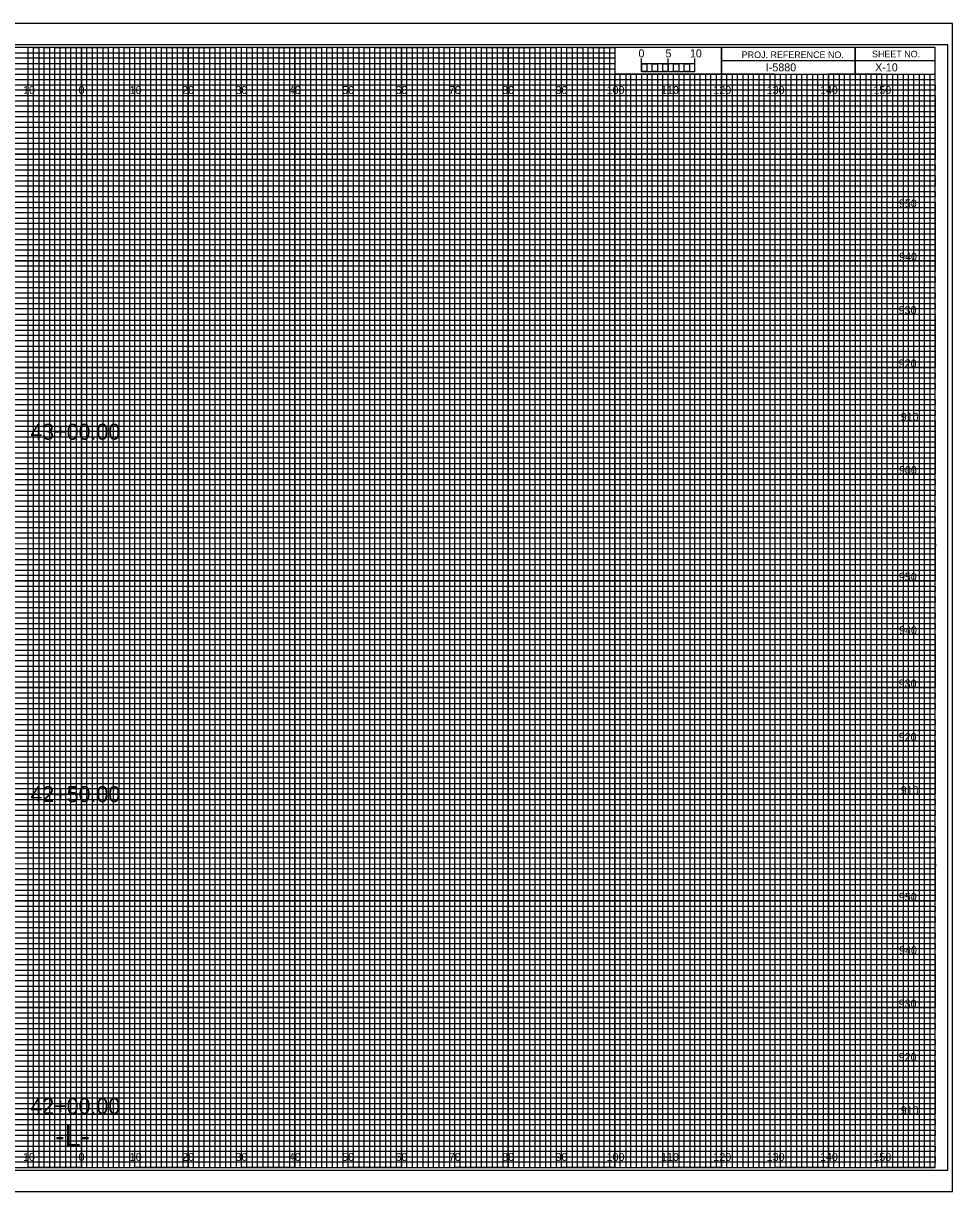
# Model space of a CAD drawing. Extents: x -13 to 323, y -4 to 3074.
# Drawn here: x 149.1 to 323.3, y 1755.5 to 1974.5 of the extents above; entities that cross this region are included whole.
import ezdxf

# ---------------------------------------------------------------- set-up
doc = ezdxf.new("R2010")
doc.units = 0
for name, color, linetype in [('Prop XS Alignment Label', 7, 'Continuous'), ('Prop XS Bar Scale Labels', 7, 'Continuous'), ('Prop XS Elevation Labels', 7, 'Continuous'), ('Prop XS Offset Labels', 7, 'Continuous'), ('Prop XS Project Number', 7, 'Continuous'), ('Prop XS Sheet Number', 7, 'Continuous'), ('Prop XS Station Labels', 7, 'Continuous'), ('Sheet Cross Section CELL', 7, 'Continuous'), ('Sheet Cross Section Grid Major CELL', 7, 'Continuous'), ('Sheet Cross Section Grid Middle CELL', 7, 'Continuous'), ('Sheet Cross Section Grid Minor 1 CELL', 7, 'Continuous'), ('Sheet Cross Section Grid Minor 2 CELL', 7, 'Continuous'), ('Sheet Cross Section Scale CELL', 7, 'Continuous'), ('Sheet Cutting Line CELL', 7, 'Continuous'), ('Sheet DOT Grid CELL', 7, 'Continuous'), ('Sheet Plot Border Inside CELL', 7, 'Continuous'), ('Sheet Plot Border Outside CELL', 7, 'Continuous')]:
    doc.layers.add(name, color=color, linetype=linetype)

msp = doc.modelspace()

# ---------------------------------------------------------------- linework, layer by layer
at = {"layer": 'Sheet Cross Section CELL'}
for p, q in [((305, 1970), (305, 1965)), ((305, 1965), (305, 1970)), ((280, 1967.5), (280, 1965)), ((320, 1967.49), (280, 1967.49)), ((280, 1965), (320, 1965))]:
    msp.add_line(p, q, dxfattribs=at)
for points in [[(320, 1970), (0, 1970), (0, 1760), (320, 1760)], [(280, 1970), (260, 1970), (260, 1965.03), (280, 1965.03)], [(320, 1970), (280, 1970), (280, 1965), (320, 1965)]]:
    msp.add_lwpolyline(points, close=True, dxfattribs=at)
at = {"layer": 'Sheet Cross Section Grid Major CELL'}
for p, q in [((150, 1970), (140, 1970)), ((150, 1760), (150, 1970)), ((170, 1970), (160, 1970)), ((160, 1970), (160, 1760)), ((170, 1760), (170, 1970)), ((190, 1970), (180, 1970)), ((180, 1970), (180, 1760)), ((190, 1760), (190, 1970)), ((210, 1970), (200, 1970)), ((200, 1970), (200, 1760)), ((210, 1760), (210, 1970)), ((230, 1970), (220, 1970)), ((220, 1970), (220, 1760)), ((230, 1760), (230, 1970)), ((250, 1970), (240, 1970)), ((240, 1970), (240, 1760)), ((250, 1760), (250, 1970)), ((260, 1970), (260, 1760)), ((270, 1760), (270, 1965)), ((290, 1965), (280, 1965)), ((280, 1965), (280, 1760)), ((290, 1760), (290, 1965)), ((310, 1965), (300, 1965)), ((300, 1965), (300, 1760)), ((310, 1760), (310, 1965)), ((160, 1760), (150, 1760)), ((180, 1760), (170, 1760)), ((200, 1760), (190, 1760)), ((220, 1760), (210, 1760)), ((240, 1760), (230, 1760)), ((260, 1760), (250, 1760)), ((280, 1760), (270, 1760)), ((300, 1760), (290, 1760)), ((320, 1760), (310, 1760)), ((320, 1760), (320, 1760))]:
    msp.add_line(p, q, dxfattribs=at)
for points in [[(0, 1960), (320, 1960), (320, 1950), (0, 1950)], [(0, 1940), (320, 1940), (320, 1930), (0, 1930)], [(0, 1920), (320, 1920), (320, 1910), (0, 1910)], [(0, 1900), (320, 1900), (320, 1890), (0, 1890)], [(0, 1880), (320, 1880), (320, 1870), (0, 1870)], [(0, 1860), (320, 1860), (320, 1850), (0, 1850)], [(0, 1840), (320, 1840), (320, 1830), (0, 1830)], [(0, 1820), (320, 1820), (320, 1810), (0, 1810)], [(0, 1800), (320, 1800), (320, 1790), (0, 1790)], [(0, 1780), (320, 1780), (320, 1770), (0, 1770)]]:
    msp.add_lwpolyline(points, dxfattribs=at)
at = {"layer": 'Sheet Cross Section Grid Middle CELL'}
for points in [[(145, 1760), (155, 1760), (155, 1970), (165, 1970), (165, 1760), (175, 1760), (175, 1970), (185, 1970), (185, 1760), (195, 1760), (195, 1970), (205, 1970), (205, 1760), (215, 1760), (215, 1970), (225, 1970), (225, 1760), (235, 1760), (235, 1970), (245, 1970), (245, 1760), (255, 1760), (255, 1970), (259.93, 1970), (260, 1970), (260, 1965), (264.99, 1965), (264.99, 1760), (275, 1760), (275, 1965), (285, 1965), (285, 1760), (295, 1760), (295, 1965), (305, 1965), (305, 1760), (315, 1760), (315, 1965)], [(0, 1965), (275, 1965)], [(0, 1945), (320, 1945), (320, 1955), (0, 1955)], [(0, 1925), (320, 1925), (320, 1935), (0, 1935)], [(0, 1905), (320, 1905), (320, 1915), (0, 1915)], [(0, 1885), (320, 1885), (320, 1895), (0, 1895)], [(0, 1865), (320, 1865), (320, 1875), (0, 1875)], [(0, 1845), (320, 1845), (320, 1855), (0, 1855)], [(0, 1825), (320, 1825), (320, 1835), (0, 1835)], [(0, 1805), (320, 1805), (320, 1815), (0, 1815)], [(0, 1785), (320, 1785), (320, 1795), (0, 1795)], [(0, 1765), (320, 1765), (320, 1775), (0, 1775)]]:
    msp.add_lwpolyline(points, dxfattribs=at)
at = {"layer": 'Sheet Cross Section Grid Minor 1 CELL'}
for p, q in [((0, 1969), (260, 1969)), ((260, 1969), (260, 1967.98)), ((260, 1967.98), (0, 1967.98)), ((0, 1967), (260, 1967)), ((260, 1967), (260, 1965.89)), ((260, 1965.89), (0, 1965.89)), ((0, 1964), (320, 1964))]:
    msp.add_line(p, q, dxfattribs=at)
for points in [[(0, 1963), (270, 1963), (320, 1963), (320, 1962), (0, 1962)], [(0, 1961), (320, 1961), (320, 1959), (0, 1959)], [(0, 1958), (320, 1958), (320, 1957), (0, 1956.98)], [(0, 1956), (320, 1956), (320, 1954), (0, 1954)], [(0, 1953), (320, 1953), (320, 1952), (0, 1952)], [(0, 1951), (320, 1951), (320, 1949), (0, 1949)], [(0, 1948), (320, 1948), (320, 1947), (0, 1947)], [(0, 1946), (320, 1946), (320, 1944), (0, 1944)], [(0, 1943), (320, 1943), (320, 1942), (0, 1942)], [(0, 1941), (320, 1941), (320, 1939), (0, 1939)], [(0, 1938), (320, 1938), (320, 1937), (0, 1937)], [(0, 1936), (320, 1936), (320, 1933.95), (320, 1933), (320, 1932), (0, 1932)], [(0, 1934), (320, 1934), (320, 1933), (0, 1933)], [(0, 1931), (320, 1931), (320, 1929), (0, 1929.03)], [(0, 1929.03), (320, 1929), (320, 1928), (0, 1928)], [(0, 1927), (320, 1927), (320, 1926), (0, 1926)], [(0, 1924), (320, 1924), (320, 1923), (0, 1923)], [(0, 1922), (320, 1922), (320, 1921), (0, 1921)], [(-0.07, 1918.89), (320, 1918.89), (320, 1917.88), (-0.07, 1917.88)], [(0, 1917), (320, 1917), (320, 1916), (0, 1916)], [(0, 1914), (320, 1914), (320, 1913), (0, 1913)], [(0, 1912), (320, 1912), (320, 1911), (0, 1911)], [(0, 1909), (320, 1909), (320, 1908), (0, 1908)], [(0, 1907), (320, 1907), (320, 1906), (0, 1906)], [(0, 1904), (320, 1904), (320, 1903), (0, 1903)], [(0, 1902), (320, 1902), (320, 1901), (0, 1901)], [(0, 1899), (320, 1899), (319.99, 1897.98), (0, 1898)], [(0, 1897), (320, 1897), (320, 1896), (0, 1896)], [(0, 1894), (320, 1894), (320, 1893), (0, 1893)], [(0, 1892), (320, 1892), (320, 1891), (0, 1891)], [(0, 1889), (320, 1889), (320, 1888), (0, 1888)], [(0, 1887), (320, 1887), (320, 1886), (0, 1886)], [(0, 1884), (320, 1884), (320, 1883), (0, 1883)], [(0, 1882), (320, 1882), (320, 1881), (0, 1881)], [(0, 1879), (320, 1879), (320, 1878), (0, 1878)], [(0, 1876.99), (320.07, 1876.91), (320, 1876), (0, 1876)], [(0, 1874), (320, 1874), (320, 1873), (0, 1873)], [(0, 1872), (320, 1872), (320, 1871), (0, 1871)], [(0, 1869), (320, 1869), (320, 1868), (0, 1868)], [(0, 1867), (320, 1867), (320, 1866), (0, 1866)], [(0, 1864), (320, 1864), (320, 1863), (0, 1863)], [(0, 1862), (320, 1862), (320, 1861), (0, 1861)], [(0, 1859), (320, 1859), (320, 1858), (0, 1858)], [(0, 1857), (320, 1857), (320, 1856), (0, 1856)], [(0, 1854), (320, 1854), (320, 1853), (0, 1853)], [(0, 1852), (320, 1852), (320, 1851), (0, 1851)], [(0, 1849), (320, 1849), (320, 1848), (0, 1848)], [(0, 1847), (320, 1847), (320, 1846), (0, 1846)], [(0, 1844), (320, 1844), (320, 1843), (0, 1843)], [(0, 1842), (320, 1842), (320, 1841), (0, 1841)], [(0, 1839), (320, 1839), (319.99, 1837.98), (0, 1838)], [(0, 1837), (320, 1837), (320, 1836), (0, 1836)], [(0, 1834), (320, 1834), (320, 1833), (0, 1833)], [(0, 1832), (320, 1832), (320, 1831), (0, 1831)], [(0, 1829), (320, 1829), (320, 1828), (0, 1828)], [(0, 1827), (320, 1827), (320, 1826), (0, 1826)], [(0, 1824), (320, 1824), (320, 1823), (0, 1823)], [(0, 1822), (320, 1822), (320, 1821), (0, 1821)], [(0, 1819), (320, 1819), (320, 1818), (0, 1818)], [(0, 1816.99), (320.07, 1816.91), (320, 1816), (0, 1816)], [(0, 1814), (320, 1814), (320, 1813), (0, 1813)], [(0, 1812), (320, 1812), (320, 1811), (0, 1811)], [(0, 1809), (320, 1809), (320, 1808), (0, 1808)], [(0, 1807), (320, 1807), (320, 1806), (0, 1806)], [(0, 1804), (320, 1804), (320, 1803), (0, 1803)], [(0, 1802), (320, 1802), (320, 1801), (0, 1801)], [(0, 1799), (320, 1799), (320, 1798), (0, 1798)], [(0, 1797), (320, 1797), (320, 1796), (0, 1796)], [(0, 1794), (320, 1794), (320, 1793), (0, 1793)], [(0, 1792), (320, 1792), (320, 1791), (0, 1791)], [(0, 1789), (320, 1789), (320, 1788), (0, 1788)], [(0, 1787), (320, 1787), (320, 1786), (0, 1786)], [(0, 1784), (320, 1784), (320, 1783), (0, 1783)], [(0, 1782), (320, 1782), (320, 1781), (0, 1781)], [(0, 1779), (320, 1779), (320, 1778), (0, 1778)], [(0, 1777), (320, 1777), (320, 1776), (0, 1776)], [(0, 1774), (320, 1774), (320, 1773), (0, 1773)], [(0, 1772), (320, 1772), (320, 1771), (0, 1771)], [(0, 1769), (320, 1769), (320, 1768), (0, 1768)], [(0, 1767), (320, 1767), (320, 1766), (0, 1766)], [(0, 1764), (320, 1764), (320, 1763), (0, 1763)], [(0, 1762), (320, 1762), (320, 1761), (0, 1761)]]:
    msp.add_lwpolyline(points, dxfattribs=at)
at = {"layer": 'Sheet Cross Section Grid Minor 2 CELL'}
for p, q in [((267, 1965), (266.01, 1965)), ((266.01, 1965), (266.01, 1760)), ((267, 1760), (267, 1965)), ((269, 1965), (268, 1965)), ((268, 1965), (268, 1760)), ((269, 1760), (269, 1965)), ((266.01, 1760), (265, 1760)), ((268, 1760), (267, 1760))]:
    msp.add_line(p, q, dxfattribs=at)
for points in [[(150, 1760), (151, 1760), (151, 1970), (152, 1970), (152, 1760)], [(152, 1760), (153, 1760), (153, 1970), (154, 1970), (154, 1760)], [(155, 1760), (156, 1760), (156, 1970), (157, 1970), (157, 1760)], [(157, 1760), (158, 1760), (158, 1970), (159, 1970), (159, 1760)], [(160, 1760), (161, 1760), (161, 1970), (162, 1970), (162, 1760)], [(162, 1760), (163, 1760), (163, 1970), (164, 1970), (164, 1760)], [(165, 1760), (166, 1760), (166, 1970), (167, 1970), (167, 1760)], [(167, 1760), (168, 1760), (168, 1970), (169, 1970), (169, 1760)], [(170, 1760), (171, 1760), (171, 1970), (172, 1970), (172, 1760)], [(172, 1760), (173, 1760), (173, 1970), (174, 1970), (174, 1760)], [(175, 1760), (176, 1760), (176, 1970), (177, 1970), (177, 1760)], [(177, 1760), (178, 1760), (178, 1970), (179, 1970), (179, 1760)], [(180, 1760), (181, 1760), (181, 1970), (182, 1970), (182, 1760)], [(182, 1760), (183, 1760), (183, 1970), (184, 1970), (184, 1760)], [(185, 1760), (186, 1760), (186, 1970), (187, 1970), (187, 1760)], [(187, 1760), (188, 1760), (188, 1970), (189, 1970), (189, 1760)], [(190, 1760), (191, 1760), (191, 1970), (192, 1970), (192, 1760)], [(192, 1760), (193, 1760), (193, 1970), (194, 1970), (194, 1760)], [(195, 1760), (196, 1760), (196, 1970), (197, 1970), (197, 1760)], [(197, 1760), (198, 1760), (198, 1970), (199, 1970), (199, 1760)], [(200, 1760), (201, 1760), (201, 1970), (202, 1970), (202, 1760)], [(202, 1760), (203, 1760), (203, 1970), (204, 1970), (204, 1760)], [(205, 1760), (206, 1760), (206, 1970), (207, 1970), (207, 1760)], [(207, 1760), (208, 1760), (208, 1970), (209, 1970), (209, 1760)], [(210, 1760), (211, 1760), (211, 1970), (212, 1970), (212, 1760)], [(212, 1760), (213, 1760), (213, 1970), (214, 1970), (214, 1760)], [(215, 1760), (216, 1760), (216, 1970), (217, 1970), (217, 1760)], [(217, 1760), (218, 1760), (218, 1970), (219, 1970), (219, 1760)], [(220, 1760), (221, 1760), (221, 1970), (222, 1970), (222, 1760)], [(222, 1760), (223, 1760), (223, 1970), (224, 1970), (224, 1760)], [(225, 1760), (226, 1760), (226, 1970), (227, 1970), (227, 1760)], [(227, 1760), (228, 1760), (228, 1970), (229, 1970), (229, 1760)], [(230, 1760), (231, 1760), (231, 1970), (232, 1970), (232, 1760)], [(232, 1760), (233, 1760), (233, 1970), (234, 1970), (234, 1760)], [(235, 1760), (236, 1760), (236, 1970), (237, 1970), (237, 1760)], [(237, 1760), (238, 1760), (238, 1970), (239, 1970), (239, 1760)], [(240, 1760), (241, 1760), (241, 1970), (242, 1970), (242, 1760)], [(242, 1760), (243, 1760), (243, 1970), (244, 1970), (244, 1760)], [(245, 1760), (246, 1760), (246, 1970), (247, 1970), (247, 1760)], [(247, 1760), (248, 1760), (248, 1970), (249, 1970), (249, 1760)], [(250, 1760), (251, 1760), (251, 1970), (252, 1970), (252, 1760)], [(252, 1760), (253, 1760), (253, 1970), (254, 1970), (254, 1760)], [(255, 1760), (256, 1760), (256, 1970), (257, 1970), (257, 1760)], [(257, 1760), (258, 1760), (258, 1970), (259, 1970), (259, 1760)], [(260, 1760), (261, 1760), (261, 1965), (262.02, 1965), (262.02, 1760)], [(262, 1760), (263, 1760), (263, 1965), (263.99, 1965), (263.99, 1760)], [(270, 1760), (270.98, 1760), (270.98, 1965), (272, 1965), (272, 1760)], [(272, 1760), (273, 1760), (273, 1965), (274.05, 1965), (274.05, 1760)], [(275, 1760), (276, 1760), (276, 1965), (277, 1965), (277, 1760)], [(277, 1760), (278, 1760), (278, 1965), (279, 1965), (279, 1760)], [(280, 1760), (281, 1760), (281, 1965), (282, 1965), (282, 1760)], [(282, 1760), (283, 1760), (283, 1965), (284, 1965), (284, 1760)], [(285, 1760), (286, 1760), (286, 1965), (287, 1965), (287, 1760)], [(287, 1760), (288, 1760), (288, 1965), (289, 1965), (289, 1760)], [(290, 1760), (291, 1760), (291, 1965), (292, 1965), (292, 1760)], [(292, 1760), (293, 1760), (293, 1965), (294, 1965), (294, 1760)], [(295, 1760), (296, 1760), (296, 1965), (297, 1965), (297, 1760)], [(297, 1760), (298, 1760), (298, 1965), (299, 1965), (299, 1760)], [(300, 1760), (301, 1760), (301, 1965), (302, 1965), (302, 1760)], [(302, 1760), (303, 1760), (303, 1965), (304, 1965), (304, 1760)], [(305, 1760), (306, 1760), (306, 1965), (307, 1965), (307, 1760)], [(307, 1760), (308, 1760), (308, 1965), (309, 1965), (309, 1760)], [(310, 1760), (311, 1760), (311, 1965), (312, 1965), (312, 1760)], [(312, 1760), (313, 1760), (313, 1965), (314, 1965), (314, 1760)], [(315, 1760), (316, 1760), (316, 1965), (317, 1965), (317, 1760)], [(317, 1760), (318, 1760), (318, 1965), (319, 1965), (319, 1760)]]:
    msp.add_lwpolyline(points, dxfattribs=at)
at = {"layer": 'Sheet Cross Section Scale CELL'}
for p, q in [((265, 1965.49), (265, 1967.9)), ((265, 1966.9), (265, 1967.9)), ((270, 1965.49), (270, 1967.9)), ((275, 1965.49), (275, 1967.9)), ((275, 1966.9), (275, 1967.9))]:
    msp.add_line(p, q, dxfattribs=at)
for points in [[(275, 1966.9), (265, 1966.9), (265, 1965.49), (275, 1965.49)], [(265, 1966.9), (266, 1966.9), (266, 1965.49), (265, 1965.49)], [(267, 1966.9), (268, 1966.9), (268, 1965.49), (267, 1965.49)], [(269, 1966.9), (270, 1966.9), (270, 1965.49), (269, 1965.49)], [(271, 1966.9), (272, 1966.9), (272, 1965.49), (271, 1965.49)], [(273, 1966.9), (274, 1966.9), (274, 1965.49), (273, 1965.49)]]:
    msp.add_lwpolyline(points, close=True, dxfattribs=at)
at = {"layer": 'Sheet Cutting Line CELL'}
for p, q in [((323.3, 1974.5), (-13.4, 1974.5)), ((-13.4, 1755.5), (323.3, 1755.5))]:
    msp.add_line(p, q, dxfattribs=at)
at = {"layer": 'Sheet DOT Grid CELL'}
for p, q in [((150, 1760), (150, 1970)), ((160, 1760), (160, 1970)), ((170, 1760), (170, 1970)), ((180, 1760), (180, 1970)), ((190, 1760), (190, 1970)), ((200, 1760), (200, 1970)), ((210, 1760), (210, 1970)), ((220, 1760), (220, 1970)), ((230, 1760), (230, 1970)), ((240, 1760), (240, 1970)), ((250, 1760), (250, 1970)), ((260, 1760), (260, 1964.69)), ((270, 1760), (270, 1964.69)), ((280, 1760), (280, 1964.69)), ((290, 1760), (290, 1964.69)), ((300, 1760), (300, 1964.69)), ((310, 1760), (310, 1964.69)), ((0, 1960), (320, 1960)), ((0, 1950), (320, 1950)), ((0, 1940), (320, 1940)), ((0, 1930), (320, 1930)), ((0, 1920), (320, 1920)), ((0, 1910), (320, 1910)), ((0, 1900), (320, 1900)), ((0, 1890), (320, 1890)), ((0, 1880), (320, 1880)), ((0, 1870), (320, 1870)), ((0, 1860), (320, 1860)), ((0, 1850), (320, 1850)), ((0, 1840), (320, 1840)), ((0, 1830), (320, 1830)), ((0, 1820), (320, 1820)), ((0, 1810), (320, 1810)), ((0, 1800), (320, 1800)), ((0, 1790), (320, 1790)), ((0, 1780), (320, 1780)), ((0, 1770), (320, 1770))]:
    msp.add_line(p, q, dxfattribs=at)
at = {"layer": 'Sheet Plot Border Inside CELL'}
msp.add_lwpolyline([(-10.8, 1759.5), (322.4, 1759.5), (322.4, 1970.5), (-10.8, 1970.5)], close=True, dxfattribs=at)
at = {"layer": 'Sheet Plot Border Outside CELL'}
msp.add_lwpolyline([(-13.4, 1755.5), (323.3, 1755.5), (323.3, 1974.5), (-13.4, 1974.5)], close=True, dxfattribs=at)

# ---------------------------------------------------------------- texts
at = {"layer": 'Prop XS Alignment Label'}
msp.add_text('-L-', height=4, dxfattribs=at).set_placement((155.06, 1764))
at = {"layer": 'Prop XS Bar Scale Labels'}
for s, p in [('5', (269.47, 1968.12)), ('10', (274.04, 1968.12))]:
    msp.add_text(s, height=1.5, dxfattribs=at).set_placement(p)
at = {"layer": 'Prop XS Elevation Labels'}
for s, p in [('950', (313.22, 1940)), ('940', (313.26, 1930)), ('930', (313.18, 1920)), ('920', (313.19, 1910)), ('910', (313.57, 1900)), ('900', (313.24, 1890)), ('950', (313.22, 1870)), ('940', (313.26, 1860)), ('930', (313.18, 1850)), ('920', (313.19, 1840)), ('910', (313.57, 1830)), ('950', (313.22, 1810)), ('940', (313.26, 1800)), ('930', (313.18, 1790)), ('920', (313.19, 1780)), ('910', (313.57, 1770))]:
    msp.add_text(s, height=1.5, dxfattribs=at).set_placement(p)
at = {"layer": 'Prop XS Offset Labels'}
for s, p in [('10', (149.04, 1961.25)), ('0', (159.45, 1961.25)), ('0', (159.45, 1961.25)), ('10', (169.04, 1961.25)), ('20', (178.86, 1961.25)), ('30', (188.86, 1961.25)), ('40', (198.86, 1961.25)), ('50', (208.86, 1961.25)), ('60', (218.86, 1961.25)), ('70', (228.86, 1961.25)), ('80', (238.86, 1961.25)), ('90', (248.86, 1961.25)), ('100', (258.44, 1961.25)), ('110', (268.62, 1961.25)), ('120', (278.44, 1961.25)), ('130', (288.44, 1961.25)), ('140', (298.44, 1961.25)), ('150', (308.44, 1961.25)), ('10', (149.04, 1761.25)), ('0', (159.45, 1761.25)), ('0', (159.45, 1761.25)), ('10', (169.04, 1761.25)), ('20', (178.86, 1761.25)), ('30', (188.86, 1761.25)), ('40', (198.86, 1761.25)), ('50', (208.86, 1761.25)), ('60', (218.86, 1761.25)), ('70', (228.86, 1761.25)), ('80', (238.86, 1761.25)), ('90', (248.86, 1761.25)), ('100', (258.44, 1761.25)), ('110', (268.62, 1761.25)), ('120', (278.44, 1761.25)), ('130', (288.44, 1761.25)), ('140', (298.44, 1761.25)), ('150', (308.44, 1761.25))]:
    msp.add_text(s, height=1.5, dxfattribs=at).set_placement(p)
at = {"layer": 'Prop XS Project Number'}
msp.add_text('I-5880', height=1.5, dxfattribs=at).set_placement((288.28, 1965.5))
at = {"layer": 'Prop XS Sheet Number'}
msp.add_text('X-10', height=1.5, dxfattribs=at).set_placement((308.77, 1965.5))
at = {"layer": 'Prop XS Station Labels'}
for s, p in [('43+00.00', (150.41, 1896.45)), ('42+50.00', (150.41, 1828.52)), ('42+00.00', (150.41, 1770.05))]:
    msp.add_text(s, height=3, dxfattribs=at).set_placement(p)
at = {"layer": 'Sheet Cross Section CELL'}
for s, p in [('PROJ. REFERENCE NO.', (283.77, 1967.99)), ('SHEET NO.', (308.19, 1968.12))]:
    msp.add_text(s, height=1.25, dxfattribs=at).set_placement(p)
at = {"layer": 'Sheet Cross Section Scale CELL'}
msp.add_text('0', height=1.5, dxfattribs=at).set_placement((264.41, 1968.12))

doc.saveas('drawing.dxf')
